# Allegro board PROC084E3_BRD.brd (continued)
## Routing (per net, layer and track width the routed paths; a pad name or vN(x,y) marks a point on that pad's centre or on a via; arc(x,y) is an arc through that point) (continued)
VCC_5V0: length 60.2
  BOTTOM w0.254: v1(80.25,168.19) C78.1 C80.1 79.46,166.82 U12.8 ; v1(27.58,188.7) C63.2 26.36,189.01 C64.1 24.87,188.86 U6.3 ; v1(41.67,112.43) C110.1 41.01,112.42 U25.4 ; v1(73.85,168.19) C79.1 C81.1 73.06,166.82 U13.8 ; v1(65.74,166.26) C83.1 C85.1 64.96,164.89 U14.8 ; v1(27.46,164.19) C86.2 26.23,164.5 C87.1 24.87,164.48 U11.3 ; U17.8 82.18,159.15 C96.1 C90.1 v1(82.96,160.52) ; v1(89.14,160.52) C89.1 C95.1 88.35,159.15 U16.8 ; U15.3 24.75,158.38 C101.1 26.36,158.53 C100.2 v1(27.46,158.35) ; v1(27.46,170.28) C75.2 26.23,170.59 C76.1 24.87,170.58 U9.3 ; U18.8 75.93,159.15 C97.1 C91.1 v1(76.72,160.52) ; v1(59.29,160.52) C93.1 C99.1 58.51,159.15 U20.8 ; v1(53.61,101.12) C122.1 52.95,101.12 U28.4 ; v1(27.46,176.51) C71.2 26.23,176.82 C72.1 24.75,176.67 U8.3 ; U7.3 24.75,182.77 C67.1 26.23,182.91 C66.2 v1(27.46,182.6) ; v1(70.01,160.52) C92.1 C98.1 69.22,159.15 U19.8
  vias: v1(98.13,68.13) v1(98.13,67.13) v1(99.27,68.13) v1(99.27,67.13)
VCC_12V0: length 2.9
  TOP w0.508: 34.51,138.81 34.51,138.77 ; 34.52,135.85 34.52,135.89
  BOTTOM w0.635: D8.2 v1(34.21,137) ; D16.2 v1(34.33,154.73) ; D12.2 v1(34.25,145.83)
VCC_PROFIB: length 15.5
  TOP w0.254: 14.45,117.39 14.44,117.38 14.44,112.32 14.62,112.14 R4.2 15.77,111.2 16.21,110.76 18.01,110.76 18.28,111.03 v1(18.28,111.05) ; J18.6 8.05,113.94 C8.2
  BOTTOM w0.254: v1(18.28,111.05) 18.3,111.05 18.37,111.12 C113.1 19.18,111.3 U26.16
VCC_RS485: length 6.1
  BOTTOM w0.254: R163.2 v1(34.5,103.68) ; U26.4 32.86,107.49 C115.2 33.07,107.7 C114.2 v1(36.02,107.7)
  vias: v1(33.96,119.39) v1(33.96,117.97)
VDD_1V0: length 59.1
  TOP w0.254: C52.1 58.75,44.21 v1(58.9,44.36) ; v1(39.22,93.89) 39.12,93.8 U3.42 ; U5.24 41.62,53.53 C44.1 v1(41.8,52.59) ; v1(39.04,62.8) 39.12,62.72 U5.42 ; v1(52.83,75.58) 52.84,75.58 C26.1 ; v1(44.63,81.12) 44.06,81.69 C23.1 ; U3.31 43.06,89.43 v1(43.28,89.65) 43.51,89.42 C15.1 ; C51.1 49.91,44.59 v1(49.91,44.59) ; U5.31 43.06,58.69 v1(43.28,58.92) 43.51,58.69 C40.1 ; U3.6 v1(34.29,89.43) ; C27.1 61.67,75.2 v1(61.82,75.35) ; U3.24 41.62,84.27 C19.1 v1(41.8,83.33) ; v1(57.66,71.38) 57.62,71.38 57.28,71.72 C33.1 C32.1 v1(53.99,72.17) ; U5.6 v1(34.29,58.69) ; v1(51.07,41.18) C56.1 C57.1 54.36,40.78 v1(54.66,40.48) ; C48.1 v1(44.61,50.95)
  BOTTOM w0.254: C172.1 59.13,44.59 v1(58.9,44.36) 58.68,44.59 U37.31 ; v1(57.66,71.38) 57.66,71.39 U30.42 ; U37.6 v1(49.91,44.59) ; v1(57.42,50.69) C168.1 57.24,49.75 U37.24 ; U37.42 54.74,40.56 v1(54.66,40.48) ; v1(39.04,62.8) 38.99,62.8 38.73,62.55 C155.1 C156.1 v1(35.45,62.1) ; C140.1 v1(63.16,83.32) ; v1(35.45,92.83) C134.1 C133.1 38.73,93.28 39.22,93.77 v1(39.22,93.89) ; C159.1 43.13,59.07 v1(43.28,58.92) ; C137.1 34.29,89.42 v1(34.29,89.43) ; U30.24 60.16,80.73 C144.1 v1(60.34,81.68) ; U30.31 61.6,75.58 v1(61.82,75.35) 62.05,75.58 C148.1 ; C136.1 43.13,89.8 v1(43.28,89.65) ; C160.1 34.29,58.69 v1(34.29,58.69) ; U30.6 v1(52.83,75.58) ; C164.1 59.91,52.33 60.1,52.52 v1(60.14,52.52)
VDD_1V8: length 5.4
  BOTTOM w0.254: 69.21,70.62 U31.7 ; 69.21,70.62 68.06,70.62 ; 69.21,70.62 69.19,70.63 C150.1 67.27,70.63 67.09,70.81 R194.2
VDD_2V5: length 22.2
  TOP w0.254: C28.1 52.81,74.06 v1(52.83,74.08) ; C17.1 34.26,87.9 v1(34.29,87.93) U3.9 ; v1(49.91,46.09) 49.89,46.12 C49.1 ; U3.3 v1(34.29,90.93) 34.27,90.95 C13.1 ; U5.3 v1(34.29,60.19) 34.27,60.21 C39.1 ; v1(52.83,77.08) 52.81,77.1 C24.1 ; C42.1 34.26,57.16 v1(34.29,57.19) U5.9 ; v1(49.91,43.09) 49.89,43.07 C54.1 ; R7.1 v1(50.42,100.09)
  BOTTOM w0.254: C17.1 34.26,87.9 v1(34.29,87.93) ; C28.1 52.81,74.06 v1(52.83,74.08) U30.3 ; U30.9 v1(52.83,77.08) 52.81,77.1 C24.1 ; U37.9 v1(49.91,46.09) 49.89,46.12 C49.1 ; C42.1 34.26,57.16 v1(34.29,57.19) ; C54.1 49.89,43.07 v1(49.91,43.09) U37.3 ; C39.1 34.27,60.21 v1(34.29,60.19) ; v1(34.29,90.93) 34.27,90.95 C13.1
VDD_IO_PHY: length 119.9
  TOP w0.254: U3.41 39.62,93.37 39.9,93.64 v1(39.91,93.64) ; v1(46.72,94.66) 46.72,94.65 46.38,94.32 R179.1 ; R288.2 R287.2 79.36,61.9 77.78,63.48 62.35,63.48 61.21,64.62 v1(61.21,66.59) ; C25.1 61.49,76.47 v1(61.82,76.14) ; v1(39.64,52.59) C43.1 39.64,53.36 39.12,53.88 U5.19 ; U5.41 39.62,62.65 v1(39.78,62.8) 39.78,62.91 v1(39.14,63.54) ; R180.1 46.18,92.03 46.74,92.59 v1(46.74,92.85) ; v1(62.35,40.7) 62.75,41.1 62.75,42.75 v1(62.29,43.21) 62.74,43.21 63.27,43.75 63.27,44.62 62.74,45.15 v1(58.9,45.15) 58.87,45.12 58.51,45.12 C50.1 ; C47.1 v1(40.02,50.95) ; C22.1 v1(40.02,81.69) ; U4.5 26.41,67.96 C38.1 26.36,68.61 26.72,68.98 v1(27.86,68.98) ; v1(39.64,83.33) C18.1 39.64,84.1 39.12,84.62 U3.19 ; U5.30 43.22,58.19 v1(43.28,58.13) 43.34,58.19 44.33,58.19 C41.1 ; v1(35.31,97.6) R10.1 R11.1 R12.1 R13.1 R14.1 R15.1 ; C58.1 55.5,40.58 v1(55.4,40.48) ; U2.5 27.63,100.17 C9.1 v1(27.58,100.95) ; C34.1 58.42,71.47 58.45,71.44 v1(58.45,71.39) ; R222.1 46.46,63.55 v1(46.51,63.5) ; v1(35.31,66.87) R52.1 R53.1 R54.1 R55.1 R56.1 R57.1 ; C16.1 44.33,88.93 43.34,88.93 v1(43.28,88.86) 43.22,88.93 U3.30
  TOP w0.381: R223.1 v1(46.53,62.15)
  BOTTOM w0.254: U30.41 58.16,71.71 58.45,71.43 v1(58.45,71.39) ; C132.1 39.7,93.01 39.7,93.4 39.79,93.48 39.79,93.52 v1(39.91,93.64) ; v1(55.4,40.48) 55.24,40.63 U37.41 ; C171.1 59.95,45.09 58.96,45.09 v1(58.9,45.15) 58.84,45.09 U37.30 ; v1(50.93,36.41) R256.1 R255.1 R254.1 R253.1 R252.1 R251.1 ; C165.1 v1(55.64,52.33) ; R84.1 v1(62.35,40.7) ; R79.1 61.76,43.21 v1(62.29,43.21) ; C161.1 42.89,58.16 43.25,58.16 v1(43.28,58.13) ; U38.5 C175.1 v1(50.65,32) ; 50.26,59.56 C158.1 ; C158.1 U33.5 ; C158.1 v1(51.49,59.56) v1(52.42,59.56) ; R201.1 R202.1 R203.1 R204.1 R205.1 R206.1 53.85,67.68 v1(54.13,67.4) ; C141.1 v1(58.56,83.32) ; C147.1 62.87,76.08 61.89,76.08 v1(61.82,76.14) 61.76,76.08 U30.30 ; R39.1 v1(65.07,70.56) ; v1(39.78,62.8) 39.65,62.68 39.65,62.32 C154.1 ; R38.1 64.79,72.84 v1(65.36,72.28) ; U30.19 57.66,80.39 58.18,80.91 C145.1 v1(58.18,81.68) ; v1(43.28,88.86) 43.25,88.9 42.89,88.9 C138.1 ; v1(55.26,50.69) C169.1 55.26,49.92 54.74,49.4 U37.19
BP/MC_PRG1_UART0_RXD: length 155.6
  TOP w0.173: J16.5 69.82,141.66 v1(69.82,137.68)
  L06_SIG2 w0.102: J24.27 57.91,16.55 57.33,17.13 53.81,17.13 36.64,34.31 36.64,57.01 39.72,60.09 39.72,60.66 41.1,62.04 41.1,71.06 50.27,80.23 50.27,93.11 56.13,98.97 56.13,108.87 v1(64.01,116.74)
  BOTTOM w0.173: v1(69.82,137.68) 69.82,120.21 65.74,116.12 64.87,116.12 64.25,116.74 v1(64.01,116.74) U23.6
BP/MC_PRG1_UART0_TXD: length 152.1
  TOP w0.173: J16.7 v1(68.51,137.68)
  L06_SIG2 w0.102: v1(56,116.09) 49.44,109.53 49.44,103.06 49.33,102.95 49.33,102.57 49.44,102.46 49.44,101.79 49.1,101.45 49.1,92.73 49.44,92.39 49.44,81.18 40.61,72.36 40.61,62.3 39.37,61.05 37.13,61.05 35.18,59.09 35.18,34.06 40.34,28.91 40.34,24.88 47.91,17.31 J24.37
  BOTTOM w0.173: v1(68.51,137.68) 68.51,127.8 63.97,123.26 59.7,123.26 58.65,122.2 58.65,116.25 58.5,116.09 U23.10 v1(56,116.09)
BP_GPIO1: length 178.3
  TOP w0.173: U44.3 63.73,21.43 v1(64.67,22.37) ; v1(70.76,140.45) 71.15,140.45 73.79,137.81 97.39,137.81 99.92,135.27 99.92,106.85 v1(97.82,104.74)
  L06_SIG2 w0.102: v1(90.58,24.12) 93.01,26.56 93.01,32.94 96.65,36.57 96.65,72.08 98.76,74.19 98.76,103.8 v1(97.82,104.74)
  BOTTOM w0.173: R149.1 v1(70.76,140.45) ; v1(64.67,22.37) 65.38,23.08 84.86,23.08 85.85,24.07 90.53,24.07 v1(90.58,24.12)
BP_GPIO2: length 185.9
  TOP w0.173: J16.9 65.97,141.77 67.56,140.17 67.56,137.63 68.25,136.95 97.03,136.95 99.06,134.92 99.06,108.75 v1(97.79,107.48) ; U44.6 v1(62.44,23.38)
  L06_SIG2 w0.102: v1(97.79,107.48) 97.79,107.13 99.21,105.7 99.21,74 97.1,71.89 97.1,36.38 93.47,32.75 93.47,25.52 v1(91.14,23.18)
  BOTTOM w0.173: v1(91.14,23.18) 87.1,23.18 85.6,21.68 64.62,21.68 62.92,23.38 v1(62.44,23.38)
BP_GPIO3: length 206.6
  TOP w0.173: U44.10 v1(53.89,24.03) ; J16.15 58.35,138.95 59.18,138.11 66.27,138.11 67.84,136.54 96.86,136.54 98.65,134.75 98.65,109.62 v1(97.74,108.7)
  L06_SIG2 w0.102: v1(90.37,21.38) 90.47,21.38 93.73,24.63 93.73,32.65 97.36,36.28 97.36,71.79 99.47,73.9 99.47,106.8 97.74,108.52 v1(97.74,108.7)
  BOTTOM w0.173: v1(53.89,24.03) 53.37,23.51 53.37,21.33 54,20.69 89.69,20.69 v1(90.37,21.38)
BP_GPIO4: length 247.4
  TOP w0.173: v1(71.55,139.18) 73.3,137.43 97.23,137.43 99.54,135.12 99.54,107.94 v1(97.82,106.21) ; U44.13 v1(53.89,22.08)
  L03_SIG1 w0.102: J5.20 52.17,188.61 51.84,188.28 51.84,173.62 67.36,158.1 67.36,139.51 67.69,139.18 v1(71.55,139.18)
  L06_SIG2 w0.102: v1(90.32,22.32) 90.32,23.1 93.24,26.02 93.24,32.85 96.88,36.48 96.88,71.99 98.98,74.1 98.98,104.99 97.82,106.16 v1(97.82,106.21)
  BOTTOM w0.173: v1(90.32,22.32) 87.27,22.32 86.26,21.3 55.52,21.3 54.71,22.11 53.92,22.11 v1(53.89,22.08)
BP_MCASP10_ACLKX: length 28.8
  TOP w0.173: R279.2 v1(57.63,149.65) ; U41.33 v1(53.71,128.63)
  L03_SIG1 w0.102: v1(57.63,149.65) 57.06,149.09 54.97,149.09 49.86,143.98 49.86,132.48 v1(53.71,128.63)
BP_MCASP10_AFSX: length 32.7
  TOP w0.173: U41.31 v1(52.71,128.63) ; R281.2 v1(60.89,149.65)
  L03_SIG1 w0.102: v1(52.71,128.63) 49.53,131.81 49.53,144.13 55.63,150.23 60.31,150.23 v1(60.89,149.65)
BP_MCASP10_AXR0: length 25.9
  TOP w0.173: R275.2 v1(54.36,149.65) ; U41.29 v1(51.71,128.63)
  L03_SIG1 w0.102: v1(51.71,128.63) 49.2,131.14 49.2,144.49 v1(54.36,149.65)
BP_MCASP10_AXR1: length 148.9
  TOP w0.173: R276.2 v1(81.8,55.63)
  L03_SIG1 w0.102: v1(94.92,61.41) 93.78,60.26 88.98,60.26 84.81,56.1 82.26,56.1 v1(81.8,55.63)
  L06_SIG2 w0.102: J16.20 53.27,145.94 54.43,147.11 76.63,147.11 77.7,146.04 77.7,139.44 78.23,138.9 95.66,138.9 99.66,134.91 99.66,124.63 97.59,122.56 97.59,111.11 97.23,110.76 97.23,102.55 97.59,102.2 97.59,73.82 94.92,71.15 v1(94.92,61.41)
BP_PRG1_PWM0_B0: length 75.9
  TOP w0.173: J5.11 63.43,183.49 61.95,182.01 56.31,182.01 48.08,173.78 48.08,134.56 52.38,130.27 57.61,130.27 59.21,128.67 U41.44
BP_PRG1_PWM0_B1: length 72.8
  TOP w0.173: U41.42 58.21,128.78 57.07,129.91 52.1,129.91 47.7,134.31 47.7,174.36 57.1,183.76 57.1,187.36 J5.16
BP_PRG1_PWM0_B2: length 69.6
  TOP w0.173: J5.18 54.54,187.34 54.54,183.18 46.79,175.43 46.79,133.9 51.49,129.2 53.98,129.2 54.71,128.47 U41.35
BP_PRG1_PWM2_A0: length 22.3
  TOP w0.173: U41.48 61.21,128.65 58.72,131.13 v1(53.77,131.13)
  L03_SIG1 w0.102: J16.17 55.81,136.79 55.7,136.68 55.7,136.3 55.81,136.19 55.81,133.17 v1(53.77,131.13)
BP_PRG1_PWM2_A1: length 17.1
  TOP w0.173: v1(54.97,129.02) 55.4,129.02 55.71,128.71 U41.37
  L03_SIG1 w0.102: J16.19 52.68,142.3 52.68,131.31 v1(54.97,129.02)
BP_PRG1_PWM3_A0: length 89.4
  TOP w0.173: U41.53 63.71,128.46 60.17,131.99 52.43,131.99 49.35,135.07 49.35,172.81 56.85,180.3 72.77,180.3 76.13,183.66 J5.1
BP_PRG1_PWM3_A2: length 83.9
  TOP w0.173: J5.5 71.05,182.5 70.03,181.47 56.57,181.47 48.49,173.4 48.49,134.77 52.63,130.62 58.19,130.62 60.21,128.61 U41.46
BP_PRG1_PWM3_B0: length 87.2
  TOP w0.173: J5.3 73.59,183.49 71.02,180.91 56.72,180.91 48.97,173.17 48.97,134.89 52.23,131.64 59.77,131.64 62.71,128.7 U41.51
BP_PRG1_PWM3_B1: length 75.6
  TOP w0.173: v1(55.5,183.25) 47.22,174.97 47.22,134.08 51.74,129.55 56.64,129.55 57.21,128.99 U41.40
  BOTTOM w0.173: R283.1 v1(55.5,183.25)
CAN1_H: length 15.4
  BOTTOM w0.127: U15.7 17.45,159.65 16.97,159.18 8.89,159.18 8.66,159.4 8.66,161.1 8.35,161.41 R129.1 7.35,161.94 J14.1
CAN1_L: length 14.8
  BOTTOM w0.127: U15.6 17.45,158.38 16.97,158.86 8.89,158.86 8.66,158.64 8.66,157.44 8.35,157.13 R130.2 7.6,156.86 J14.3
CAN1_RXD: length 2.1
  BOTTOM w0.173: U15.4 23.99,157.11 24.37,156.73 R131.2
CAN1_T: length 2.5
  BOTTOM w0.173: R129.2 8.11,160.2 C94.1 8.11,158.35 R130.1
CAN2_H: length 9.5
  BOTTOM w0.127: J12.1 13.19,167.91 R118.1 14.22,167.38 14.53,167.07 14.53,165.4 14.66,165.27 17.02,165.27 17.5,165.75 U11.7
CAN2_L: length 9.2
  BOTTOM w0.127: U11.6 17.48,164.48 17,164.96 14.66,164.96 14.53,164.83 14.53,163.41 14.22,163.1 R121.2 13.44,162.83 J12.3
CAN2_RXD: length 2.1
  BOTTOM w0.173: U11.4 24.4,163.21 R126.2
CAN2_T: length 2.5
  BOTTOM w0.173: R118.2 13.95,166.17 C84.1 13.95,164.32 R121.1
CAN3_H: length 15.5
  BOTTOM w0.127: J10.1 7.22,174.64 R114.1 8.38,173.99 8.69,173.68 8.69,172.15 8.81,172.02 12.88,172.02 13.53,171.37 17.02,171.37 17.5,171.85 U9.7
CAN3_L: length 15.1
  BOTTOM w0.127: J10.3 7.73,169.56 R115.2 7.87,169.75 8.69,170.56 8.69,171.58 8.81,171.71 12.75,171.71 13.4,171.05 17.02,171.05 17.5,170.58 U9.6
CAN3_RXD: length 2.1
  BOTTOM w0.173: U9.4 24.4,169.31 R117.2
CAN3_T: length 2.5
  BOTTOM w0.173: R114.2 8.11,172.77 C74.1 8.11,170.92 R115.1
CAN4_H: length 9.6
  BOTTOM w0.127: U8.7 17.48,177.94 17,177.46 14.78,177.46 14.53,177.71 14.53,179.39 14.22,179.7 R111.1 13.19,180.23 J8.1
CAN4_L: length 9
  BOTTOM w0.127: U8.6 17.48,176.67 17,177.15 14.73,177.15 14.53,176.95 14.53,175.73 14.22,175.42 R112.2 13.44,175.15 J8.3
CAN4_RXD: length 2
  BOTTOM w0.173: U8.4 24.4,175.4 R113.2
CAN4_T: length 2.5
  BOTTOM w0.173: R112.1 13.95,176.64 C70.1 13.95,178.49 R111.2
CAN5_H: length 15.2
  BOTTOM w0.127: J6.1 7.35,186.07 R108.1 8.35,185.54 8.66,185.23 8.66,183.69 8.79,183.56 17,183.56 17.48,184.04 U7.7
CAN5_L: length 15.1
  BOTTOM w0.127: U7.6 17.5,182.77 17.02,183.25 8.81,183.25 8.69,183.12 8.69,181.57 8.38,181.26 R109.2 7.6,180.99 J6.3
CAN5_RXD: length 1.9
  BOTTOM w0.173: U7.4 24.53,181.5 R110.2
CAN5_T: length 2.5
  BOTTOM w0.173: R109.1 8.11,182.48 C68.1 8.11,184.33 R108.2
CAN6_H: length 9.6
  BOTTOM w0.127: U6.7 17.48,190.13 17,189.66 16.28,189.66 15.93,190.01 14.68,190.01 14.55,190.13 14.55,191.71 14.24,192.02 R105.1 13.19,192.55 J3.1
CAN6_L: length 9.3
  BOTTOM w0.127: U6.6 17.5,188.86 17.02,189.34 16.15,189.34 15.8,189.69 14.83,189.69 14.55,189.42 14.55,188.05 14.24,187.74 R106.2 13.44,187.47 10.92,187.47
CAN6_RXD: length 2
  BOTTOM w0.173: R107.2 24.66,187.59 U6.4
CAN6_T: length 2.5
  BOTTOM w0.173: R105.2 13.95,190.8 C62.1 13.95,188.95 R106.1
CAN_STB: length 150.8
  TOP w0.173: v1(93.58,122.01) 93.08,122.51 J1.102
  L06_SIG2 w0.102: v1(44.2,133.55) 51.88,125.86 83.61,125.86 84.44,125.03 93.32,125.03 94.16,124.19 94.16,122.59 v1(93.58,122.01)
  BOTTOM w0.173: U6.8 19.81,191.4 19.96,191.25 19.96,185.59 19.68,185.31 ; 19.68,185.31 20,184.99 20,179.58 19.63,179.21 ; 19.68,185.31 U7.8 ; 19.63,167.02 19.94,167.32 19.94,172.76 19.58,173.12 ; 19.63,167.02 19.66,167.02 19.99,166.69 19.99,162.1 18.81,160.92 ; 19.63,167.02 U11.8 ; U9.8 19.58,173.12 ; 19.58,173.12 20.02,173.55 20.02,178.83 19.63,179.21 ; v1(93.58,122.01) 93.58,122.01 R152.1 R151.2 ; 19.63,179.21 U8.8 ; 18.81,160.92 18.93,160.92 20.08,159.77 20.08,156.8 21.33,155.55 40.86,155.55 44.2,152.21 v1(44.2,133.55) ; 18.81,160.92 U15.8
CON_MCU_ADC1_AIN0: length 119.9
  TOP w0.173: J2.83 85.87,68.63 85.95,68.55 85.97,68.55 86.26,68.26 v1(86.29,68.26)
  BOTTOM w0.173: U17.6 80.88,158.44 81.05,158.61 81.41,158.61 81.53,158.49 U17.7 81.53,156.76 81.61,156.68 83.75,156.68 84.84,157.77 84.84,160.63 85.94,161.73 88.62,161.73 90.74,159.61 90.74,150.79 89.19,149.24 89.19,129.05 87.72,127.58 87.72,122.32 89.12,120.92 89.12,111.55 91.06,109.61 91.06,87.91 90.4,87.25 90.4,76.23 92.07,74.56 92.07,68.42 90.99,67.34 87.21,67.34 v1(86.29,68.26)
CON_MCU_ADC1_AIN1: length 123.1
  TOP w0.173: v1(84.01,69.04) 84.06,69.04 84.15,69.13 J2.85
  BOTTOM w0.173: v1(84.01,69.04) 84.04,69.01 84.08,69.01 86.09,66.99 91.14,66.99 92.42,68.28 92.42,74.71 90.75,76.37 90.75,87.1 91.45,87.81 91.45,111.1 90.67,111.88 90.67,119.97 88.71,121.93 88.71,128.08 89.53,128.9 89.53,149.09 91.09,150.65 91.09,159.75 86.71,164.12 78.98,164.12 78.81,164.3 U12.7 78.81,166.16 78.69,166.28 78.33,166.28 78.16,166.11 U12.6
CON_MCU_ADC1_AIN2: length 139.5
  TOP w0.173: J2.87 83.93,69.63 83.93,69.64 83.48,69.64 83.42,69.58 v1(83.47,69.58)
  BOTTOM w0.173: v1(83.47,69.58) 83.47,68.84 83.88,68.43 84.17,68.43 85.96,66.63 91.27,66.63 92.76,68.13 92.76,74.85 91.09,76.52 91.09,86.81 91.8,87.51 91.8,111.25 91.02,112.03 91.02,121.26 90.41,121.87 90.41,128.31 89.94,128.79 89.94,149.01 91.43,150.5 91.43,159.9 81.92,169.41 78.38,169.41 75.34,166.37 75.34,162.3 74.5,161.46 74.5,158.57 74.63,158.44 ; 74.63,158.44 74.8,158.61 75.16,158.61 75.28,158.49 U18.7 ; 74.63,158.44 U18.6
CON_MCU_ADC1_AIN3: length 140.6
  TOP w0.173: J2.89 v1(82.98,70.13)
  BOTTOM w0.173: v1(82.98,70.13) 82.97,70.13 82.97,68.5 83.42,68.05 83.42,67.02 84.15,66.29 91.41,66.29 93.11,67.99 93.11,75.02 91.44,76.68 91.44,86.67 92.89,88.12 92.89,93.62 93,93.73 93,110.53 91.36,112.17 91.36,121.41 90.76,122.01 90.76,128.46 90.28,128.93 90.28,148.72 91.78,150.22 91.78,160.04 82.07,169.75 78.23,169.75 74.99,166.51 74.99,165.94 73.4,164.35 72.47,164.35 72.41,164.41 U13.7 72.41,166.16 72.29,166.28 71.93,166.28 71.76,166.11 U13.6
CON_MCU_ADC1_AIN4: length 155.1
  TOP w0.173: v1(82.4,69.36) 82.4,70.46 82.57,70.63 J2.91
  BOTTOM w0.173: U19.7 68.57,158.49 68.45,158.61 68.1,158.61 ; v1(82.4,69.36) 82.35,69.31 82.35,66.95 83.36,65.94 91.55,65.94 93.56,67.95 93.56,74.04 93.9,74.37 93.9,75.64 93.61,75.93 93.19,75.93 91.79,77.34 91.79,86.51 94.14,88.86 94.14,107.77 93.38,108.53 93.38,111.91 91.71,113.58 91.71,121.55 91.15,122.11 91.15,128.71 90.63,129.24 90.63,148.58 92.12,150.08 92.12,160.18 82.21,170.1 72.67,170.1 67.77,165.2 67.77,158.71 67.87,158.61 68.1,158.61 ; U19.6 67.92,158.44 68.1,158.61
CON_MCU_ADC1_AIN5: length 155.8
  TOP w0.173: J2.93 v1(84.01,71.13)
  BOTTOM w0.173: U14.6 63.66,164.18 63.83,164.35 64.19,164.35 64.31,164.23 U14.7 64.31,162.63 64.52,162.42 66.46,162.42 66.95,162.91 66.95,164.87 72.52,170.44 82.35,170.44 92.47,160.32 92.47,149.59 90.97,148.09 90.97,129.43 91.5,128.9 91.5,122.25 92.23,121.52 92.64,121.52 92.93,121.23 92.93,112.85 93.72,112.05 93.72,112.03 93.75,112.01 93.75,109.58 94.6,108.73 94.6,108.71 95.13,108.18 95.13,74.81 93.97,73.66 93.97,67.88 91.69,65.6 83.21,65.6 81.91,66.9 81.91,69.75 83.28,71.13 v1(84.01,71.13)
CON_MCU_ADC1_AIN6: length 168
  TOP w0.173: J2.95 83.32,71.63 82.89,72.06 v1(82.52,72.06)
  BOTTOM w0.173: 57.38,158.61 57.73,158.61 57.86,158.49 U20.7 ; 57.38,158.61 57.18,158.61 57.06,158.72 57.06,161.38 66.47,170.79 82.49,170.79 92.81,160.47 92.81,149.45 91.32,147.95 91.32,129.57 91.84,129.05 91.84,123.37 93.08,122.13 93.08,121.81 93.37,121.52 93.77,121.52 94.2,121.08 94.2,109.78 95.47,108.51 95.47,74.67 94.32,73.52 94.32,67.73 91.84,65.25 83.07,65.25 81.56,66.76 81.56,71.11 v1(82.52,72.06) ; 57.38,158.61 57.21,158.44 U20.6
CON_MCU_ADC1_AIN7: length 109.8
  TOP w0.173: J2.97 v1(83.97,72.13)
  BOTTOM w0.173: v1(83.97,72.13) 84.5,71.61 84.5,69.61 85.35,68.75 86.5,68.75 87.56,67.69 90.85,67.69 91.73,68.56 91.73,74.42 90.06,76.09 90.06,87.39 90.72,88.05 90.72,109.46 88.78,111.4 88.78,120.77 87.38,122.17 87.38,127.72 88.84,129.19 88.84,149.38 90.4,150.93 90.4,156.29 90.13,156.56 87.91,156.56 87.7,156.76 U16.7 87.7,158.49 87.58,158.61 87.22,158.61 87.05,158.44 U16.6
EEPROM_A0: length 9.4
  TOP w0.173: J2.19 82.29,47.63 v1(79.87,45.22)
  BOTTOM w0.173: U36.1 R237.2 v1(79.87,45.22)
EEPROM_A1: length 10.8
  TOP w0.173: v1(78.6,45.22) 81.52,48.13 J2.21
  BOTTOM w0.173: U36.2 R238.2 v1(78.6,45.22)
EEPROM_A2: length 12.3
  TOP w0.173: v1(77.33,45.22) 80.75,48.63 J2.23
  BOTTOM w0.173: v1(77.33,45.22) R239.2 U36.3
EEPROM_WP: length 12.2
  TOP w0.173: v1(78.52,53.37) 78.52,51.17 80.57,49.13 J2.25
  BOTTOM w0.173: U36.7 R228.2 v1(78.52,53.37)
EHRPWM0_A: length 27.9
  TOP w0.173: R277.2 v1(81.89,52.72)
  L06_SIG2 w0.102: J22.7 79.51,28.98 79.51,41.67 81.89,44.04 v1(81.89,52.72)
EHRPWM0_A/MCASP10_AXR1: length 5.6
  TOP w0.173: J2.47 85.11,54.65 R276.1 R277.1
EHRPWM0_B: length 33.4
  TOP w0.173: v1(82.78,55.63) 83.28,55.13 J2.49
  L06_SIG2 w0.102: J22.9 76.96,28.97 76.96,32.11 77.87,33.02 77.87,41.16 80.98,44.26 80.98,53.83 v1(82.78,55.63)
EHRPWM0_SYNCI/MCASP10_ACLKX: length 144.9
  TOP w0.173: v1(82.86,52.63) 83.36,53.13 J2.41 ; U41.23 v1(54.21,136.13)
  L03_SIG1 w0.102: v1(82.86,52.63) 83.36,53.13 84.43,53.13 85.09,53.79 85.09,54.9 89.43,59.25 94.39,59.25 v1(94.87,58.77)
  L06_SIG2 w0.102: v1(54.21,136.13) 55.58,137.51 66.09,137.51 66.73,138.14 95.35,138.14 98.89,134.59 98.89,124.95 96.82,122.88 96.82,111.77 96.37,111.32 96.37,102.07 96.82,101.61 96.82,74.14 93.88,71.19 93.88,59.76 v1(94.87,58.77)
EHRPWM0_SYNCO/MCASP10_AFSX: length 142.2
  TOP w0.173: J2.43 v1(84.01,53.63) ; U41.25 v1(53.21,136.13)
  L03_SIG1 w0.102: v1(94.92,59.68) 89.38,59.68 84.01,54.3 v1(84.01,53.63)
  L06_SIG2 w0.102: v1(94.92,59.68) 94.16,60.44 94.16,71.13 97.06,74.04 97.06,101.77 96.62,102.21 96.62,111.17 97.06,111.61 97.06,122.78 99.13,124.85 99.13,134.69 95.45,138.38 66.59,138.38 65.98,137.77 54.84,137.77 v1(53.21,136.13)
EHRPWM1_A: length 39.5
  TOP w0.173: v1(82.73,56.73) 82.76,56.73 83.36,56.13 J2.53
  L06_SIG2 w0.102: v1(82.73,56.73) 82.73,57.06 83.24,57.57 83.24,58.08 83.06,58.26 82.45,58.26 80.44,56.25 80.44,44.83 75.08,39.47 75.08,33.39 74.55,32.86 74.55,29.1 J22.11
EHRPWM1_B: length 29.5
  TOP w0.173: J2.51 v1(84.01,55.63)
  L06_SIG2 w0.102: v1(84.01,55.63) 84.34,55.63 86.39,53.58 86.39,43.83 83.95,41.39 83.95,32.15 J22.2
EHRPWM2_A: length 42.8
  TOP w0.173: v1(84,56.68) 84.05,56.63 J2.55
  L06_SIG2 w0.102: J22.6 82.09,28.92 82.09,26.68 82.78,26 86.74,26 87.15,26.4 87.15,38.52 87.68,39.05 87.68,53 v1(84,56.68)
EHRPWM2_B: length 36.1
  TOP w0.173: J2.61 84.54,63.13 v1(84.01,62.6)
  L06_SIG2 w0.102: v1(84.01,62.6) 83.54,62.13 83.54,57.29 83.26,57.01 83.26,55.08 81.2,53.02 81.2,44.17 78.23,41.2 J22.8
EHRPWM_TZN_IN0/MCASP10_AXR0: length 145.2
  TOP w0.173: U41.27 v1(52.21,136.13) ; J2.45 83.36,54.13 v1(82.86,53.63)
  L03_SIG1 w0.102: v1(94.89,60.52) 94.41,60.04 89.27,60.04 v1(82.86,53.63)
  L06_SIG2 w0.102: v1(52.21,136.13) 54.12,138.04 65.87,138.04 66.48,138.65 95.56,138.65 99.41,134.81 99.41,124.74 97.34,122.67 97.34,111.42 96.93,111.01 96.93,102.41 97.34,102 97.34,73.92 94.44,71.02 94.44,60.97 v1(94.89,60.52)
EHRPWM_TZN_IN1: length 30.7
  TOP w0.173: J2.59 84.12,57.63 v1(84,57.75)
  L06_SIG2 w0.102: v1(84,57.75) 84,57.42 83.52,56.94 83.52,55.39 85.57,53.33 85.57,43.34 83.54,41.3 83.54,30.47 J22.4
EHRPWM_TZN_IN2: length 33.6
  TOP w0.173: J2.57 85.08,57.19 83.3,57.19 v1(82.72,57.77)
  L06_SIG2 w0.102: v1(82.72,57.77) 82.46,57.77 80.7,56 80.7,44.76 75.31,39.37 75.31,33.37 75.69,32.98 J22.10
EQEP0_A: length 56
  TOP w0.173: U44.9 58.2,24.68 59.74,26.23 v1(63.14,26.23) ; J2.11 v1(84.01,45.63)
  L03_SIG1 w0.102: v1(63.14,26.23) 64.52,24.86 86.73,24.86 87.6,25.73 87.6,42.03 v1(84.01,45.63)
EQEP0_B: length 60.2
  TOP w0.173: v1(63.17,25.29) 59.74,25.29 57.19,22.73 U44.12 ; v1(82.86,45.63) 83.26,45.63 83.76,46.13 J2.13
  L03_SIG1 w0.102: v1(82.86,45.63) 83.35,46.12 84.25,46.12 87.99,42.38 87.99,25.62 86.89,24.53 63.93,24.53 v1(63.17,25.29)
EQEP0_I: length 51.6
  TOP w0.173: J2.12 v1(90.12,45.63) ; U44.4 v1(63.18,22.08)
  L03_SIG1 w0.102: v1(90.12,45.63) 89.2,44.72 89.2,24.6 87.48,22.87 63.97,22.87 v1(63.18,22.08)
EQEP0_S: length 54.9
  TOP w0.173: v1(92.66,46.65) 92.14,46.13 J2.14 ; U44.7 v1(63.16,24.03)
  L03_SIG1 w0.102: v1(92.66,46.65) 90.32,46.65 88.85,45.18 88.85,24.83 87.25,23.23 63.96,23.23 v1(63.16,24.03)
EXP_MCAN4_RX: length 18
  TOP w0.173: J1.28 v1(92.43,99.01)
  L03_SIG1 w0.102: v1(77.93,99.5) 79.27,99.5 79.91,100.14 81.51,100.14 82.02,100.66 82.79,100.66 84.27,99.18 92.26,99.18 v1(92.43,99.01)
  BOTTOM w0.173: U29.4 v1(77.93,99.5)
EXP_MCAN4_TX: length 20.9
  TOP w0.173: J1.26 93.08,98.51 v1(93.58,98.01)
  L03_SIG1 w0.102: v1(93.58,98.01) 92.99,98.59 92.99,99.1 91.92,100.16 84.1,100.16 83.37,100.89 81.93,100.89 81.54,100.5 v1(77.93,100.5)
  BOTTOM w0.173: U29.2 v1(77.93,100.5)
EXP_MCAN5_RX: length 18.4
  TOP w0.173: J1.24 v1(92.43,98.01)
  L03_SIG1 w0.102: v1(78.95,97.5) 80.25,97.5 82.21,99.46 83.05,99.46 83.8,98.72 91.24,98.72 91.96,98.01 v1(92.43,98.01)
  BOTTOM w0.173: v1(78.95,97.5) 78.45,97 U29.9
EXP_MCAN5_TX: length 21.8
  TOP w0.173: v1(93.58,97.01) 93.08,97.51 J1.22
  L03_SIG1 w0.102: v1(93.58,97.01) 92.96,97.62 92.96,98.21 92.68,98.49 91.8,98.49 91.34,98.95 84.05,98.95 82.57,100.43 82.12,100.43 81.5,99.81 80,99.81 78.69,98.5 v1(77.93,98.5)
  BOTTOM w0.173: U29.6 v1(77.93,98.5)
EXP_MCAN6_RX: length 11.1
  TOP w0.173: J1.23 83.64,98.01 82.21,96.58 77.74,96.58 77.39,96.23 77.39,95.54 v1(77.93,95)
  BOTTOM w0.173: U29.13 v1(77.93,95)
EXP_MCAN6_TX: length 9
  TOP w0.173: J1.21 83.65,97.51 82.14,96 v1(77.93,96)
  BOTTOM w0.173: U29.11 v1(77.93,96)
EXP_MCAN7_RX: length 15.4
  TOP w0.173: J1.27 83.56,99.01 82.56,98.01 77.65,98.01 75.62,95.98 v1(75.62,92.5)
  BOTTOM w0.173: U29.18 v1(75.62,92.5)
EXP_MCAN7_TX: length 12.9
  TOP w0.173: J1.25 83.61,98.51 82.02,96.92 77.6,96.92 77.05,96.37 77.05,94.88 v1(77.93,94)
  BOTTOM w0.173: U29.15 v1(77.93,94)
EXP_PRG0_MDIO0_MDC: length 78.2
  TOP w0.173: v1(93.58,121.01) 93.08,121.51 J1.98
  L06_SIG2 w0.102: v1(90.53,61.44) 90.53,63.31 91.59,64.38 91.59,65.47 92.66,66.53 92.66,71.87 95.76,74.97 95.76,100.98 95.22,101.51 95.22,111.77 95.76,112.31 95.76,120.31 95.06,121.01 v1(93.58,121.01)
  BOTTOM w0.173: v1(90.53,61.44) 84.78,61.44 84.02,60.68 81.33,60.68 80.84,61.17 U34.4
EXP_PRG0_MDIO0_MDIO: length 81.1
  TOP w0.173: J1.100 v1(92.43,122.01)
  L03_SIG1 w0.102: v1(81.53,58.32) 84.14,58.32 86.29,60.48 88.87,60.48 88.88,60.49 93.25,60.49 93.8,61.05 93.8,73.32 95.71,75.22 95.71,110.5 94.49,111.72 94.49,121.05 94.03,121.5 92.94,121.5 v1(92.43,122.01)
  BOTTOM w0.173: v1(81.53,58.32) 81.53,58.74 81.05,59.22 U34.7
EXP_PRG1_MDIO0_MDC: length 73.5
  TOP w0.173: v1(93.58,106.01) 93.08,105.51 J1.54
  L06_SIG2 w0.102: v1(93.58,106.01) 93.07,105.5 93.07,104.92 92.66,104.51 92.25,104.51 91.59,103.85 91.59,88.19 90.86,87.45 90.86,76.54 91.14,76.26 91.14,68.64 85.57,63.07 80.38,63.07 75.99,58.68 v1(75.47,58.68)
  BOTTOM w0.173: v1(75.47,58.68) 74.31,57.53 69.68,57.53 68.43,58.78 68.43,60.69 68.08,61.05 U35.4
EXP_PRG1_MDIO0_MDIO: length 70.4
  TOP w0.173: J1.56 v1(92.43,106.01)
  L06_SIG2 w0.102: v1(76.37,59.86) 76.77,59.86 80.4,63.48 85.66,63.48 90.91,68.74 90.91,76.1 90.63,76.38 90.63,87.54 91.36,88.28 91.36,104.94 v1(92.43,106.01)
  BOTTOM w0.173: U35.7 67.59,59.1 69.59,57.1 74.91,57.1 76.37,58.56 v1(76.37,59.86)
EXP_PRG1_RGMII1_RD0: length 26.4
  TOP w0.173: J1.84 v1(92.43,118.01)
  L03_SIG1 w0.102: v1(92.43,118.01) 91.28,116.85 84.48,116.85 83.99,117.35 78.77,117.35 78.34,117.78 78.34,119.38 78.78,119.82 v1(78.8,119.82)
  BOTTOM w0.173: v1(78.8,119.82) 78.8,121.45 76,124.25 R338.1
EXP_PRG1_RGMII1_RD1: length 26.2
  TOP w0.173: J1.88 v1(92.43,119.01)
  L03_SIG1 w0.102: v1(92.43,119.01) 85.81,119.01 85.32,119.5 82.7,119.5 82.03,120.17 81.74,120.17 81.64,120.07 81.64,119.06 81.54,118.96 81.13,118.96 81.03,119.06 81.03,120.07 80.93,120.17 80.53,120.17 80.42,120.07 80.42,119.06 80.32,118.96 79.92,118.96 79.81,119.06 79.81,120.07 79.71,120.17 79.45,120.17 79.26,119.98 79.26,119.63 78.82,119.2 v1(78.82,118.84)
  BOTTOM w0.173: v1(78.82,118.84) 78.28,119.39 78.28,121.09 76.37,122.99 R351.1
EXP_PRG1_RGMII1_RD2: length 26.7
  TOP w0.173: J1.94 93.08,120.51 v1(93.58,120.01)
  L03_SIG1 w0.102: v1(78.87,117.91) 79.46,118.51 87.22,118.51 87.32,118.4 87.32,117.95 87.42,117.85 87.83,117.85 87.93,117.95 87.93,118.4 88.03,118.51 92.58,118.51 92.96,118.89 92.96,119.4 v1(93.58,120.01)
  BOTTOM w0.173: R340.1 73.97,121.73 74.41,121.29 76.11,121.29 77.65,119.75 77.65,119.13 v1(78.87,117.91)
EXP_PRG1_RGMII1_RD3: length 26.2
  TOP w0.173: v1(93.58,119.01) 93.08,119.51 J1.90
  L03_SIG1 w0.102: v1(78.95,116.8) 83.98,116.8 84.31,116.47 87.08,116.47 87.19,116.37 87.19,115.98 87.29,115.88 87.69,115.88 87.79,115.98 87.79,116.37 87.9,116.47 88.3,116.47 88.4,116.37 88.4,115.98 88.51,115.88 88.91,115.88 89.01,115.98 89.01,116.37 89.12,116.47 92.86,116.47 93.12,116.73 93.12,118.55 v1(93.58,119.01)
  BOTTOM w0.173: v1(78.95,116.8) 77.21,118.54 77.21,119.35 76.32,120.24 R341.1
EXP_PRG1_RGMII1_RX_CTL: length 26.1
  TOP w0.173: J1.92 v1(92.43,120.01)
  L03_SIG1 w0.102: v1(78.04,116.62) 77.65,117.02 77.65,119.91 78.85,121.11 79.6,121.11 80.22,120.49 92.27,120.49 92.43,120.33 v1(92.43,120.01)
  BOTTOM w0.173: v1(78.04,116.62) 78.04,116.96 76.41,118.59 74.4,118.59 74.15,118.84 R342.1
EXP_PRG1_RGMII1_RXC: length 26
  TOP w0.173: v1(93.58,118.01) 93.08,118.51 J1.86
  L03_SIG1 w0.102: v1(78.95,115.3) 79.15,115.51 86.54,115.51 86.64,115.41 86.64,114.57 86.74,114.47 87.15,114.47 87.25,114.57 87.25,115.41 87.35,115.51 93.72,115.51 94.03,115.82 94.03,117.55 v1(93.58,118.01)
  BOTTOM w0.173: v1(78.95,115.3) 78.55,115.3 76.26,117.59 R343.1
EXP_PRG1_RGMII1_TD0: length 30.8
  TOP w0.173: v1(93.58,103.01) 93.08,102.51 J1.42
  L03_SIG1 w0.102: v1(77.8,114.61) 79.01,113.4 79.01,112.24 80.69,110.56 87.98,110.56 92.02,106.52 92.63,106.52 93.04,106.11 93.04,105.77 93.31,105.5 93.78,105.5 94.08,105.2 94.08,103.51 v1(93.58,103.01)
  BOTTOM w0.173: R344.1 73.91,116.29 74.36,115.84 76.57,115.84 v1(77.8,114.61)
EXP_PRG1_RGMII1_TD1: length 30.4
  TOP w0.173: J1.50 93.08,104.51 v1(93.58,105.01)
  L03_SIG1 w0.102: v1(77.48,113.08) 77.19,112.79 75.9,112.79 75.68,113.01 75.68,113.27 76.55,114.14 77.73,114.14 78.67,113.21 78.67,112.15 80.52,110.3 87.4,110.3 92.24,105.46 92.67,105.46 93.13,105.01 v1(93.58,105.01)
  BOTTOM w0.173: v1(77.48,113.08) 77.48,114.08 76.48,115.07 R345.1
EXP_PRG1_RGMII1_TD2: length 30.5
  TOP w0.173: v1(93.58,104.01) 93.08,103.51 J1.46
  L03_SIG1 w0.102: v1(93.58,104.01) 93.03,104.55 92.19,104.55 86.89,109.85 80.48,109.85 79.57,110.76 79.43,110.76 78.8,110.13 78.66,110.13 78.37,110.42 78.37,110.56 79,111.19 79,111.33 77.95,112.38 77.42,112.38 77.24,112.19 77.24,111.92 v1(77.81,111.35)
  BOTTOM w0.173: v1(77.81,111.35) 77.81,111.67 76.06,113.42 R346.1
EXP_PRG1_RGMII1_TD3: length 30.4
  TOP w0.173: J1.40 v1(92.43,102.01)
  L03_SIG1 w0.102: v1(77.85,110.55) 76.67,111.72 75.99,111.72 75.57,111.3 75.57,107.44 76.39,106.62 79.16,106.62 80.18,107.63 85.78,107.63 91.4,102.01 v1(92.43,102.01)
  BOTTOM w0.173: R347.1 76.23,112.19 77.85,110.57 v1(77.85,110.55)
EXP_PRG1_RGMII1_TX_CTL: length 30.7
  TOP w0.173: J1.44 v1(92.43,103.01)
  L03_SIG1 w0.102: v1(92.43,103.01) 92.33,103.01 87.43,107.91 80.14,107.91 79.07,106.85 76.54,106.85 75.87,107.52 75.87,109.48 76.14,109.74 77.06,109.74 77.16,109.64 77.16,109.07 v1(77.93,108.3)
  BOTTOM w0.173: v1(77.93,108.3) 77.93,108.44 75.88,110.49 R360.1
EXP_PRG1_RGMII1_TXC: length 31.1
  TOP w0.173: J1.48 v1(92.43,104.01)
  L03_SIG1 w0.102: v1(92.43,104.01) 92.12,104.01 87.97,108.16 85.68,108.16 85.58,108.26 85.58,109.2 85.47,109.31 85.07,109.31 84.97,109.2 84.97,108.26 84.86,108.16 84.46,108.16 84.36,108.26 84.36,109.2 84.26,109.31 83.85,109.31 83.75,109.2 83.75,108.26 83.65,108.16 83.24,108.16 83.14,108.26 83.14,109.2 83.04,109.31 82.63,109.31 82.53,109.2 82.53,108.26 82.43,108.16 81.7,108.16 81.16,108.69 81.16,109.04 80.63,109.57 79.85,109.57 79.75,109.47 79.75,108.56 79.64,108.46 79.24,108.46 79.14,108.56 79.14,109.47 79.03,109.57 78.64,109.57 78.43,109.35 78.43,107.8 v1(77.93,107.3)
  BOTTOM w0.173: R349.1 76.44,109.22 77.07,108.59 77.07,108.17 v1(77.93,107.3)
EXP_REFCLK: length 2.8
  TOP w0.173: J2.22 v1(92.46,48.13)
  BOTTOM w0.173: TP27.1 93.74,48.13 v1(92.46,48.13)
EXP_RSTZ: length 7.5
  TOP w0.173: J1.118 90.47,126.51 v1(89.79,127.19)
  L03_SIG1 w0.102: v1(89.79,127.19) 90.74,126.24 90.74,124.47 v1(89.53,123.27)
  BOTTOM w0.173: TP24.1 v1(89.53,123.27)
FB_V1V0: length 2
  TOP w0.173: R9.1 60.96,97.19 v1(60.96,96.69)
  BOTTOM w0.173: U27.8 v1(60.96,96.69) 61.09,96.56 R177.2
FB_V1V8: length 1.9
  TOP w0.173: R6.1 40.51,108.49 v1(40.51,107.99)
  BOTTOM w0.173: U25.8 v1(40.51,107.99) 40.51,107.57 R160.2
FB_V2V5: length 1.9
  TOP w0.173: v1(52.45,96.69) 52.45,97.19 R8.1
  BOTTOM w0.173: U28.8 v1(52.45,96.69) 52.45,96.26 R176.2
GPIO_LIN_EN: length 88.9
  TOP w0.173: v1(93.58,124.01) 93.08,124.51 J1.110
  L03_SIG1 w0.102: v1(38.98,151.21) 38.98,150.83 38.99,150.82 v1(38.99,149.26) 38.99,142.4 v1(38.91,142.31) 38.91,140.37 v1(38.92,140.36) 38.92,133.53 v1(38.87,133.48) 38.87,131.54 v1(38.87,131.53)
  L06_SIG2 w0.102: v1(93.58,124.01) 93.12,123.55 92.24,123.55 92.03,123.77 88.95,123.77 88.14,124.58 84.54,124.58 83.51,125.61 46.44,125.61 40.52,131.53 v1(38.87,131.53)
  BOTTOM w0.173: v1(93.58,124.01) 94.12,124.55 R150.2 94.68,125.71 94.68,125.71 R144.1 ; U45.2 v1(38.87,133.48) ; U47.2 v1(38.98,151.21) ; U45.5 v1(38.87,131.53) ; U46.2 v1(38.91,142.31) ; U47.5 v1(38.99,149.26) ; U46.5 v1(38.92,140.36)
GPIO_PRG0_RGMII1_RST: length 2.7
  BOTTOM w0.173: R245.2 R246.2 U38.2
GPIO_PRG0_RGMII2_RST: length 2.5
  TOP w0.173: R63.1 R62.2 U4.2
GPIO_PRG0_RGMII_RST: length 85
  TOP w0.173: J2.29 83.57,50.13 v1(83.08,49.65) ; R62.1 v1(27.36,60.99)
  L03_SIG1 w0.102: v1(27.36,60.99) 27.36,58.47 v1(46.79,39.04)
  BOTTOM w0.173: v1(83.08,49.65) 83.49,49.24 83.49,42.23 81.2,39.94 74.52,39.94 69.83,35.25 60.35,35.25 59.24,34.15 51.54,34.15 49.38,36.31 49.38,38.78 49.12,39.04 47.47,39.04 R246.1 v1(46.79,39.04)
GPIO_PRG1_RGMII1_RST: length 2.7
  BOTTOM w0.173: R216.2 R217.2 U33.2
GPIO_PRG1_RGMII2_RST: length 2.5
  TOP w0.173: U2.2 R20.2 R21.1
GPIO_PRG1_RGMII_RST: length 150.7
  TOP w0.173: v1(32.87,95.11) 30.38,92.62 28.96,92.62 28.57,93 R20.1 ; J1.66 v1(90.17,113.51)
  L03_SIG1 w0.102: v1(32.87,95.11) 33.68,95.93 39.7,95.93 40.46,95.16 40.46,93.49 38.35,91.38 38.35,87.03 37.11,85.79 37.11,71 45.59,62.52 45.59,61.07 45.91,60.75 46.72,60.75 47.24,60.23 48.27,60.23 50.03,61.98 50.03,64.91 v1(51.71,66.6)
  L06_SIG2 w0.102: v1(32.87,95.11) 32.87,95.98 36.35,99.46 38.33,99.46 52.78,113.91 52.78,122.24 55.68,125.15 75.3,125.15 76.16,124.29 82.91,124.29 83.73,123.47 87.05,123.47 90.32,120.2 90.32,118.68 89.71,118.07 89.71,113.97 v1(90.17,113.51)
  BOTTOM w0.173: R217.1 v1(51.71,66.6)
I2C0_SCL: length 4.3
  TOP w0.173: J1.109 83.36,124.51 82.41,123.56 TP60.1
I2C0_SDA: length 4.1
  TOP w0.173: TP61.1 82.31,125.57 82.86,125.01 J1.111
I2C1_SCL: length 4.9
  TOP w0.173: v1(81.68,126.44) 81.92,126.44 82.85,125.51 J1.113
  BOTTOM w0.173: v1(81.68,126.44) 81.25,126.02 TP25.1
I2C1_SDA: length 6
  TOP w0.173: v1(80.9,126.8) 81.37,127.27 82.6,127.27 83.86,126.01 J1.115
  BOTTOM w0.173: v1(80.9,126.8) 81.27,127.18 TP26.1
I2C3_SCL: length 3
  TOP w0.173: J2.8 v1(92.56,44.63)
  BOTTOM w0.173: TP34.1 92.56,42.97 v1(92.56,44.63)
I2C3_SDA: length 3.8
  TOP w0.173: J2.10 92.08,45.13 v1(92.56,45.61)
  BOTTOM w0.173: v1(92.56,45.61) 93.5,45.61 TP35.1
I2C5_SCL: length 121.1
  L03_SIG1 w0.102: J24.47 37.91,16.65 35.79,18.77 35.79,19.45 34.52,20.72 34.52,22.23 35.16,22.87 35.39,23.1 38.35,23.1 39.59,24.35 39.59,27.39 40.13,27.93 40.13,28.62 40.69,29.17 41.88,29.17 42.15,28.91 42.93,28.91 43.53,29.5 51.92,29.5 52.12,29.71 53.97,29.71 60.45,36.19 60.45,37.95 62.03,39.53 62.24,39.53 63.08,40.38 63.08,41.59 63.71,42.22 64.23,42.22 66.6,44.59 66.6,54.59 69.03,57.02 75.7,57.02 78.77,60.09 81.43,60.09 v1(81.53,60.19) 83.52,60.19 88.23,64.9 89.69,64.9 91.64,66.85 91.64,73.59 89.1,76.14 87.1,76.14 84.28,78.96 77.36,78.96 76.14,77.74 J19.3
  BOTTOM w0.173: U34.6 81.22,59.87 v1(81.53,60.19)
I2C5_SDA: length 116
  L03_SIG1 w0.102: J19.1 78.87,78.5 84.18,78.5 88.72,73.96 88.72,65.75 84.15,61.17 v1(81.53,61.17) 79.29,61.17 75.44,57.33 69.01,57.33 66.37,54.69 66.37,44.68 64.14,42.45 63.61,42.45 62.85,41.69 62.85,40.51 62.11,39.76 61.94,39.76 60.22,38.05 60.22,36.28 53.88,29.94 41.99,29.94 41.45,29.4 40.6,29.4 39.9,28.71 39.9,28.03 39.36,27.48 39.36,24.44 38.25,23.33 35.29,23.33 35.07,23.1 34.29,22.33 34.29,18.83 36.91,16.21 36.91,14.55 35.91,13.55 J24.50
  BOTTOM w0.173: v1(81.53,61.17) 80.88,61.82 U34.3
I2C6_SCL: length 4.4
  TOP w0.173: J2.107 84.39,74.63 83.91,75.11 83.91,76.74 v1(83.97,76.8)
  BOTTOM w0.173: TP31.1 83.97,76.32 v1(83.97,76.8)
I2C6_SDA: length 3
  TOP w0.173: v1(86.52,74.52) 85.91,75.13 J2.109
  BOTTOM w0.173: TP32.1 86.74,74.74 v1(86.52,74.52)
IMU_GPIO0: length 41.1
  L03_SIG1 w0.102: J19.7 73.26,78.89 76.7,78.89 77.17,79.36 84.48,79.36 86.07,77.78 88.03,77.78 92.91,72.9 92.91,61.7 92.65,61.44 v1(92.51,61.44)
  BOTTOM w0.173: R296.2 90.32,59.25 v1(92.51,61.44)
IMU_GPIO1: length 61.6
  L03_SIG1 w0.102: v1(81.97,112.1) 82.07,112 82.13,112 82.75,111.37 91.92,111.37 94.74,108.55 94.74,106.39 94.46,106.11 94.46,99.2 94.11,98.85 94.11,93.64 91.16,90.69 87.99,90.69 76.48,79.19 71.55,79.19 J19.9
  BOTTOM w0.173: v1(81.97,112.1) 81.97,111.41 81.66,111.09 R301.2
LIN1_DATA: length 33.8
  L03_SIG1 w0.102: v1(22.3,133.19) 24.72,135.62 34.22,135.62 v1(35.43,136.82)
  BOTTOM w0.173: J25.2 11.64,137.28 14.37,134.55 15.86,134.55 18.13,132.29 SW2.3 22.61,133.09 22.51,133.19 v1(22.3,133.19) ; v1(35.43,136.82) 35.43,135.77 C196.1 34.3,134.63 34.3,133.65 34.47,133.48 U45.13
LIN1_RXD: length 3.4
  TOP w0.173: R364.1 v1(39.93,135.14)
  BOTTOM w0.173: U45.1 38.92,134.13 39.28,134.49 R364.1 v1(39.93,135.14)
LIN1_TXD: length 3.5
  TOP w0.173: R387.2 v1(39.92,133.73)
  BOTTOM w0.173: v1(39.92,133.73) R387.2 39.72,132.83 U45.3
LIN1_UART_RXD: length 200.1
  TOP w0.173: v1(30.43,34.86) 31.22,34.08 33.02,34.08 34.19,32.91 70.82,32.91 82.54,44.63 J2.7
  L06_SIG2 w0.102: v1(30.43,34.86) 29.82,35.47 29.82,65.09 30.35,65.62 33.25,65.62 33.43,65.45 35.1,65.45 39.17,69.51 39.17,72.1 48.36,81.29 48.36,89.99 47.51,90.84 47.51,91.84 48.34,92.66 48.34,92.68 48.36,92.71 48.36,96.12 47.45,97.03 45.05,97.03 43.62,95.6 35.15,95.6 33.76,94.2 31.46,94.2 29.94,95.72 29.94,96.66 31.05,97.77 33.06,99.78 33.06,112.38 35.59,114.91 35.59,130.5 36.43,131.34 36.43,132.96 37.66,134.18 39.76,134.18 v1(40.91,135.34)
  BOTTOM w0.173: R367.1 v1(40.91,135.34)
LIN1_UART_TXD: length 196.9
  TOP w0.173: v1(31.7,34.86) 34.16,34.86 35.48,33.54 70.89,33.54 82.48,45.13 J2.9
  L06_SIG2 w0.102: v1(31.7,34.86) 31.24,35.32 30.3,35.32 30.05,35.57 30.05,65 30.45,65.39 33.15,65.39 33.33,65.22 35.2,65.22 39.4,69.41 39.4,72.01 48.84,81.45 48.84,89.85 48.17,90.53 48.17,92.03 48.64,92.5 48.64,96.27 47.4,97.52 45.17,97.52 43.48,95.82 35.06,95.82 33.66,94.43 32.42,94.43 30.86,95.99 30.86,97.26 31.15,97.54 33.32,99.72 33.32,112.31 35.82,114.81 35.82,128.81 38.42,131.41 38.42,132.36 38.84,132.78 v1(41.73,132.78)
  BOTTOM w0.173: R366.1 41.49,133.02 v1(41.73,132.78)
LIN2_DATA: length 28.3
  BOTTOM w0.173: U45.9 33.82,130.88 33.67,130.72 C197.1 33.67,129.52 33.03,128.89 23.29,128.89 22.61,129.57 SW2.4 17.92,131 14.84,134.08 13.88,134.08 12.66,135.3 J25.3
LIN2_RXD: length 3.6
  TOP w0.173: R365.1 v1(39.92,130.86)
  BOTTOM w0.173: U45.4 39.06,132.18 39.66,131.57 R365.1 v1(39.92,130.86)
LIN2_TXD: length 3.8
  TOP w0.173: R386.2 v1(39.93,129.23)
  BOTTOM w0.173: v1(39.93,129.23) R386.2 38.69,130.11 38.56,130.23 37.96,130.23 U45.7
LIN2_UART_RXD: length 102.3
  TOP w0.173: J2.84 89.73,68.63 v1(89.25,69.11)
  L03_SIG1 w0.102: v1(48.14,131.81) 48.9,131.05 48.9,128.7 57.92,119.69 57.92,115.27 68.2,104.99 83.35,104.99 84.9,103.44 84.9,102.03 84.17,101.3 v1(83.96,101.3)
  BOTTOM w0.173: v1(89.25,69.11) 87.71,69.11 85.83,70.98 85.83,71.61 84.59,72.86 84.59,74.08 82.37,76.29 82.37,99.21 83.05,99.89 83.05,100.38 v1(83.96,101.3) ; R369.1 40.9,131.05 41.22,130.73 47.05,130.73 v1(48.14,131.81)
LIN2_UART_TXD: length 102.1
  TOP w0.173: J2.86 v1(90.13,69.13)
  L03_SIG1 w0.102: v1(81.78,101.58) 82.69,101.58 83.61,102.5 84.14,102.5 84.46,102.82 84.46,103.55 83.25,104.76 68.1,104.76 57.68,115.18 57.68,119.59 48.41,128.87 v1(48.41,130.86)
  BOTTOM w0.173: R368.1 47.66,130.11 v1(48.41,130.86) ; v1(90.13,69.13) 89.61,68.62 87.71,68.62 85.49,70.84 85.49,71.43 82.04,74.88 82.04,76.13 82.03,76.15 82.03,90.38 81.73,90.68 81.73,101.53 v1(81.78,101.58)
LIN3_DATA: length 39.4
  L03_SIG1 w0.102: v1(22.34,142.03) 25.1,144.79 34.6,144.79 v1(35.47,145.66)
  BOTTOM w0.173: v1(22.34,142.03) 22.55,142.03 22.65,141.93 SW3.3 18.74,141.12 16.47,143.39 9.37,143.39 7.24,141.26 J26.2 ; U46.13 34.51,142.31 34.34,142.49 34.34,143.47 C201.1 35.47,144.61 v1(35.47,145.66)
LIN3_RXD: length 3.4
  TOP w0.173: R372.1 v1(39.97,143.98)
  BOTTOM w0.173: U46.1 38.96,142.96 39.32,143.32 R372.1 v1(39.97,143.98)
LIN3_TXD: length 3.5
  TOP w0.173: R389.2 v1(39.96,142.56)
  BOTTOM w0.173: U46.3 39.76,141.66 R389.2 v1(39.96,142.56)
LIN3_UART_RXD: length 136
  TOP w0.173: v1(89.27,70.18) 89.82,69.63 J2.88
  L06_SIG2 w0.102: v1(81.25,146.47) 81.49,146.71 81.49,149.53 78.44,152.59 62.8,152.59 62.62,152.77 51.88,152.77 43.28,144.18 v1(40.95,144.18)
  BOTTOM w0.173: v1(81.25,146.47) 81.25,143.29 79.03,141.07 79.03,127.67 79.03,127.67 79.03,125.05 81.81,122.27 81.81,116.26 82.67,115.4 83.07,115.4 83.51,114.96 83.51,108.56 84.93,107.14 84.93,91.88 83.87,90.82 83.87,86.19 83.06,85.38 83.06,79.27 85.28,77.06 85.28,73.29 86.35,72.22 86.48,72.22 87.61,71.09 87.61,70.38 88.01,69.98 89.08,69.98 v1(89.27,70.18) ; R375.1 v1(40.95,144.18)
LIN3_UART_TXD: length 136.3
  TOP w0.173: J2.90 v1(90.14,70.13)
  L06_SIG2 w0.102: v1(80.96,149.21) 80.07,150.11 67.49,150.11 65.39,152.2 62.87,152.2 62.58,152.49 52.59,152.49 41.77,141.67 v1(41.77,141.62)
  BOTTOM w0.173: R374.1 41.53,141.86 v1(41.77,141.62) ; v1(80.96,149.21) 78.9,147.15 78.9,141.43 77.84,140.36 77.84,125.59 81.33,122.1 81.33,115.69 83.16,113.86 83.16,108.11 84.53,106.75 84.53,101.01 83.53,100.01 83.53,97.22 83.51,97.21 83.51,91.8 83.53,91.79 83.53,86.33 82.72,85.52 82.72,76.44 84.93,74.22 84.93,73 86.18,71.76 86.18,71.13 87.67,69.64 89.65,69.64 v1(90.14,70.13)
LIN4_DATA: length 36
  BOTTOM w0.173: J26.3 5.95,138.72 10.14,142.91 16.03,142.91 19.11,139.83 SW3.4 22.65,138.41 23.33,137.73 33.07,137.73 33.71,138.36 C202.1 33.71,139.56 33.86,139.71 U46.9
LIN4_RXD: length 3.6
  TOP w0.173: R373.1 v1(39.96,139.69)
  BOTTOM w0.173: U46.4 39.1,141.01 39.71,140.4 R373.1 v1(39.96,139.69)
LIN4_TXD: length 3.8
  TOP w0.173: R388.2 v1(39.97,138.06)
  BOTTOM w0.173: U46.7 38,139.07 38.6,139.07 38.73,138.94 R388.2 v1(39.97,138.06)
LIN4_UART_RXD: length 135.1
  TOP w0.173: J2.92 89.88,70.63 v1(89.33,71.18)
  L06_SIG2 w0.102: v1(80.96,148.43) 79.55,149.84 66.85,149.84 64.71,151.98 54.12,151.98 v1(41.71,139.57)
  BOTTOM w0.173: v1(80.96,148.43) 83.36,146.03 83.36,143.14 80.16,139.94 80.16,124.89 82.54,122.52 83.2,122.52 83.36,122.36 83.36,117.53 85.1,115.79 85.1,108.08 85.67,107.5 85.67,92.95 87.54,91.08 87.54,78.58 85.97,77 85.97,73.62 86.56,73.03 87.48,73.03 v1(89.33,71.18) ; R377.1 40.94,139.89 41.26,139.57 v1(41.71,139.57)
LIN4_UART_TXD: length 133.2
  TOP w0.173: J2.94 v1(90.19,71.13)
  L06_SIG2 w0.102: v1(81,147.47) 66.46,147.47 63.93,150 63.93,150.55 63.66,150.81 54.74,150.81 53.32,149.39 52.54,149.39 v1(41.7,138.55)
  BOTTOM w0.173: v1(90.19,71.13) 89.75,70.69 89.13,70.69 87.25,72.56 86.54,72.56 85.62,73.48 85.62,77.2 84.3,78.52 84.3,83.11 84.31,83.12 84.31,83.53 84.3,83.54 84.3,90.76 85.27,91.73 85.27,107.38 84.68,107.98 84.68,115.04 83.97,115.75 82.85,115.75 82.15,116.44 82.15,122.42 79.66,124.91 79.66,140.61 81.8,142.75 81.8,146.67 v1(81,147.47) ; v1(41.7,138.55) 41.31,138.94 R376.1
LIN5_DATA: length 32.4
  L03_SIG1 w0.102: v1(22.41,150.93) 25.36,153.88 34.86,153.88 v1(35.54,154.56)
  BOTTOM w0.173: U47.13 34.59,151.21 34.42,151.38 34.42,152.37 C206.1 35.54,153.51 v1(35.54,154.56) ; J27.2 12.98,151.81 15.52,151.81 17.31,150.02 SW4.3 22.73,150.83 22.63,150.93 v1(22.41,150.93)
LIN5_RXD: length 3.4
  TOP w0.173: R380.1 v1(40.05,152.88)
  BOTTOM w0.173: v1(40.05,152.88) R380.1 39.4,152.22 39.04,151.86 U47.1
LIN5_TXD: length 3.5
  TOP w0.173: R390.2 v1(40.04,151.46)
  BOTTOM w0.173: U47.3 39.84,150.56 R390.2 v1(40.04,151.46)
LIN5_UART_RXD: length 135.7
  TOP w0.173: v1(89.43,72.14) 89.94,71.63 J2.96
  L06_SIG2 w0.102: v1(41.03,153.07) 41.17,153.07 44.13,156.03 81.75,156.03 86.24,151.54 86.24,147.16 v1(85.25,146.17)
  BOTTOM w0.173: v1(89.43,72.14) 87.67,73.9 87.67,76.15 87.38,76.44 87.38,77.56 87.96,78.14 87.96,91.15 86.95,92.15 86.95,109.31 85.44,110.83 85.44,115.94 84.53,116.84 84.53,121.79 83.36,122.96 83.36,123.21 82.35,124.22 82.35,139.03 84.49,141.17 84.49,145.41 v1(85.25,146.17) ; R383.1 v1(41.03,153.07)
LIN5_UART_TXD: length 134.6
  TOP w0.173: J2.98 v1(90.19,72.13)
  L06_SIG2 w0.102: v1(85.24,147.28) 85.93,147.97 85.93,151.24 82.26,154.91 82.23,154.91 82.02,155.12 46.27,155.12 41.85,150.69 v1(41.85,150.52)
  BOTTOM w0.173: R382.1 41.61,150.75 v1(41.85,150.52) ; v1(90.19,72.13) 88.06,74.26 88.06,76.27 87.72,76.61 87.72,77.32 88.3,77.9 88.3,91.29 87.3,92.29 87.3,109.46 85.79,110.97 85.79,116.08 84.88,116.99 84.88,124.76 82.79,126.85 82.79,138.98 86.32,142.51 86.32,146.2 v1(85.24,147.28)
LIN6_DATA: length 28.1
  BOTTOM w0.173: J27.3 12.73,151.46 15.31,151.46 18.04,148.73 SW4.4 22.73,147.3 23.41,146.62 33.15,146.62 33.79,147.26 C207.1 33.79,148.46 33.94,148.61 U47.9
LIN6_RXD: length 3.6
  TOP w0.173: R381.1 v1(40.04,148.59)
  BOTTOM w0.173: U47.4 39.17,149.91 39.78,149.3 R381.1 v1(40.04,148.59)
LIN6_TXD: length 3.8
  TOP w0.173: R391.2 v1(40.05,146.96)
  BOTTOM w0.173: v1(40.05,146.96) R391.2 38.8,147.84 38.68,147.96 38.08,147.96 U47.7
LIN6_UART_RXD: length 133.2
  TOP w0.173: J2.106 89.99,74.13 89.79,73.94 v1(89.79,73.88)
  L06_SIG2 w0.102: v1(41.79,148.46) 43.39,148.46 49.61,154.68 82.17,154.68 85.7,151.15 85.7,148.89 v1(85.23,148.42)
  BOTTOM w0.173: v1(41.79,148.46) 41.34,148.46 41.02,148.79 R385.1 ; v1(89.79,73.88) 88.71,74.97 88.71,91.37 87.65,92.44 87.65,109.6 86.82,110.43 86.82,118.2 85.27,119.75 85.27,124.97 83.26,126.98 83.26,138.96 86.66,142.37 86.66,146.99 v1(85.23,148.42)
LIN6_UART_TXD: length 130.4
  TOP w0.173: v1(89.79,74.71) 89.87,74.63 J2.108
  L06_SIG2 w0.102: v1(41.78,147.45) 44.88,147.45 50.94,153.51 82.96,153.51 85.13,151.34 v1(85.13,149.44)
  BOTTOM w0.173: v1(41.78,147.45) 41.38,147.84 R384.1 ; v1(85.13,149.44) 87.04,147.53 87.04,142.26 83.87,139.08 83.87,127.85 85.61,126.1 85.61,119.89 87.16,118.34 87.16,110.84 89.05,108.95 89.05,75.45 v1(89.79,74.71)
MAIN_UART4_CTSN: length 26.9
  TOP w0.173: U42.12 v1(72.27,47.58)
  BOTTOM w0.173: R295.1 86.35,55.63 84.73,57.24 76.71,57.24 72.27,52.81 v1(72.27,47.58)
MAIN_UART4_RTSN: length 35
  TOP w0.173: J2.42 91.36,53.07 93.14,53.07 v1(93.58,52.63) ; U42.4 v1(71.62,41.98)
  BOTTOM w0.173: v1(93.58,52.63) 93.14,53.07 85.19,53.07 81.71,49.6 81.71,42.81 80.09,41.19 72.42,41.19 v1(71.62,41.98)
MAIN_UART4_RXD: length 36.5
  TOP w0.173: v1(93.58,55.63) 93.08,56.13 J2.54 ; U42.7 v1(73.57,41.98)
  BOTTOM w0.173: v1(73.57,41.98) 73.57,52.18 77.55,56.15 85.17,56.15 86.61,54.7 91.57,54.7 92,55.13 93.08,55.13 v1(93.58,55.63)
MAIN_UART4_TXD: length 31.5
  TOP w0.173: U42.9 v1(74.22,47.58) ; J2.50 93.69,55.13 93.95,54.87 93.95,53.99 v1(93.56,53.6)
  BOTTOM w0.173: v1(93.56,53.6) 93.03,54.13 82.18,54.13 80.72,55.59 77.7,55.59 74.22,52.11 v1(74.22,47.58)
MC/BP_SEL: length 2.9
  TOP w0.173: R282.1 R273.1 U41.1
MC_EQEP0_A: length 23.7
  TOP w0.173: U44.11 v1(54.53,23.38)
  L03_SIG1 w0.102: J24.46 40.91,14.48 40.91,17.25 42.34,18.68 43.97,18.68 45.49,20.21 54.18,20.21 55.17,21.2 55.17,22.67 54.53,23.31 v1(54.53,23.38)
MC_EQEP0_B: length 22.1
  TOP w0.173: U44.14 v1(54.53,21.43)
  L03_SIG1 w0.102: J24.48 38.91,14.48 38.91,16.22 41.71,19.01 43.54,19.01 45.95,21.43 v1(54.53,21.43)
MC_EQEP0_I: length 21.7
  TOP w0.173: U44.2 58.44,20.78 54.71,17.06 v1(45.29,17.06)
  L03_SIG1 w0.102: v1(45.29,17.06) 44.91,16.68 44.91,14.48 J24.42
MC_EQEP0_S: length 24.3
  TOP w0.173: U44.5 v1(60.13,22.73)
  L03_SIG1 w0.102: J24.44 42.91,14.48 42.91,16.33 46,19.42 54.71,19.42 58.02,22.73 v1(60.13,22.73)
MC_PRG1_PWM0_B0: length 174.5
  TOP w0.173: U41.45 v1(59.71,126.42)
  L06_SIG2 w0.102: v1(95.1,133.97) 93.4,132.27 64.08,132.27 59.71,127.89 v1(59.71,126.42)
  BOTTOM w0.173: v1(95.1,133.97) 95.1,132.63 99.14,128.59 99.14,73.32 97.63,71.81 97.63,63.93 98.36,63.2 98.36,36.57 94.21,32.42 94.21,20.73 90.19,16.7 81.13,16.7 J24.5
MC_PRG1_PWM0_B1: length 176
  TOP w0.173: U41.43 v1(58.71,126.42)
  L06_SIG2 w0.102: v1(93.83,134) 92.43,132.6 63.88,132.6 58.71,127.43 v1(58.71,126.42)
  BOTTOM w0.173: v1(93.83,134) 93.83,132.98 98.79,128.02 98.79,73.46 97.28,71.95 97.28,63.79 98.01,63.06 98.01,36.77 93.83,32.58 93.83,20.83 90.1,17.11 79.54,17.11 J24.7
MC_PRG1_PWM0_B2: length 188.5
  TOP w0.173: U41.36 v1(55.21,126.42)
  L06_SIG2 w0.102: v1(55.21,126.42) 55.21,127.23 62.38,134.41 90.37,134.41 91.69,135.73 94.61,135.73 v1(95.1,135.24)
  BOTTOM w0.173: v1(95.1,135.24) 95.73,134.61 95.73,133.09 99.48,129.34 99.48,72.98 98.78,72.28 98.78,36.42 94.61,32.25 94.61,20.64 86.36,12.39 75,12.39 J24.12
MC_PRG1_PWM2_A0: length 181.4
  TOP w0.173: U41.50 v1(62.21,126.42)
  L06_SIG2 w0.102: v1(62.21,126.42) 66.73,130.95 92.08,130.95 v1(92.56,131.43)
  BOTTOM w0.173: J24.21 63.91,16.61 65.85,18.56 90.57,18.56 93.04,21.02 93.04,32.93 97.32,37.22 97.32,62.77 96.59,63.5 96.59,72.24 97.18,72.83 97.18,110.93 97.87,111.61 97.87,127.03 93.46,131.43 v1(92.56,131.43)
MC_PRG1_PWM2_A1: length 184.5
  TOP w0.173: U41.39 v1(56.71,126.42)
  L06_SIG2 w0.102: v1(92.56,135.24) 90.65,133.34 63.62,133.34 v1(56.71,126.42)
  BOTTOM w0.173: J24.13 71.91,16.87 73.22,18.18 90.68,18.18 93.42,20.92 93.42,32.75 97.67,37 97.67,62.91 96.94,63.65 96.94,72.1 97.66,72.82 97.66,103.46 98.31,104.11 98.31,127.87 92.56,133.62 v1(92.56,135.24)
MC_PRG1_PWM3_A0: length 180.6
  TOP w0.173: U41.54 v1(64.21,126.42)
  L06_SIG2 w0.102: v1(92.56,130.16) 67.95,130.16 v1(64.21,126.42)
  BOTTOM w0.173: v1(92.56,130.16) 93.34,129.38 94.5,129.38 97.18,126.7 97.18,111.9 96.49,111.21 96.49,73.12 95.9,72.53 95.9,63.22 96.63,62.48 96.63,38.69 92.28,34.34 92.28,21.24 90.38,19.34 62.69,19.34 59.91,16.57 J24.25
MC_PRG1_PWM3_A2: length 191.2
  TOP w0.173: U41.47 v1(60.71,126.42)
  L06_SIG2 w0.102: v1(97.64,132.7) 96.9,131.97 66.25,131.97 v1(60.71,126.42)
  BOTTOM w0.173: v1(97.64,132.7) 100.95,129.39 100.95,37.44 95.43,31.92 95.43,20.48 86.49,11.54 66.75,11.54 65.91,12.39 J24.20
MC_PRG1_PWM3_B0: length 180.8
  TOP w0.173: U41.52 v1(63.21,126.42)
  L06_SIG2 w0.102: v1(63.21,126.42) 67.43,130.65 93.34,130.65 v1(93.83,130.16)
  BOTTOM w0.173: J24.23 61.91,16.57 64.3,18.96 90.49,18.96 92.66,21.13 92.66,34.18 96.98,38.5 96.98,62.63 96.25,63.36 96.25,72.38 96.84,72.97 96.84,111.07 97.53,111.76 97.53,126.88 94.24,130.16 v1(93.83,130.16)
MC_PRG1_PWM3_B1: length 191.8
  TOP w0.173: U41.41 v1(57.71,126.42)
  L06_SIG2 w0.102: v1(96.37,135.24) 95.71,134.58 93.62,134.58 92.02,132.98 63.73,132.98 57.71,126.96 v1(57.71,126.42)
  BOTTOM w0.173: J24.16 69.91,12.39 70.41,11.89 86.35,11.89 95.02,20.56 95.02,32.09 99.83,36.89 99.83,129.68 96.37,133.14 v1(96.37,135.24)
MCAN4_RX: length 89.9
  L03_SIG1 w0.102: J15.2 40.54,157.62 43.36,154.8 43.36,124 48.68,118.68 49,118.68 67.73,99.96 70.74,99.96 v1(71.19,99.5)
  BOTTOM w0.173: U29.52 70.51,99 71.01,99.5 v1(71.19,99.5) ; R131.1 29.34,156.73 J15.2
